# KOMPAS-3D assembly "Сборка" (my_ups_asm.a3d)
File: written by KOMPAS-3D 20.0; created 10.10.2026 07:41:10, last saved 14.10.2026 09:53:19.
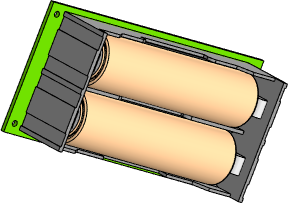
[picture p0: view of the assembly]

Document properties: Полное имя файла: D:\RicWork\Project-EPS32\box_compas\ups 18650\my_ups_asm.a3d

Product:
- Part/product: Сборка
    Масса: 0.425781
  - Component [detail]: Деталь  | qty 2  | Масса: 0.12809; source file: 18650 acc.m3d
  - Component [detail]: Деталь  | Масса: 0.0459981; source file: my_ups.m3d
  - Component [detail]: Деталь  | Масса: 0.123603; source file: battery 18650 case x2.m3d

Referenced files in D:\RicWork\Project-EPS32\box_compas\ups 18650\: my_ups.m3d, 18650 acc.m3d, battery 18650 case x2.m3d
Referenced files in D:\RicWork\Project-EPS32\box_compas\18650\: 18650 acc.m3d
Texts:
  Деталь (1)
  Деталь (2)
